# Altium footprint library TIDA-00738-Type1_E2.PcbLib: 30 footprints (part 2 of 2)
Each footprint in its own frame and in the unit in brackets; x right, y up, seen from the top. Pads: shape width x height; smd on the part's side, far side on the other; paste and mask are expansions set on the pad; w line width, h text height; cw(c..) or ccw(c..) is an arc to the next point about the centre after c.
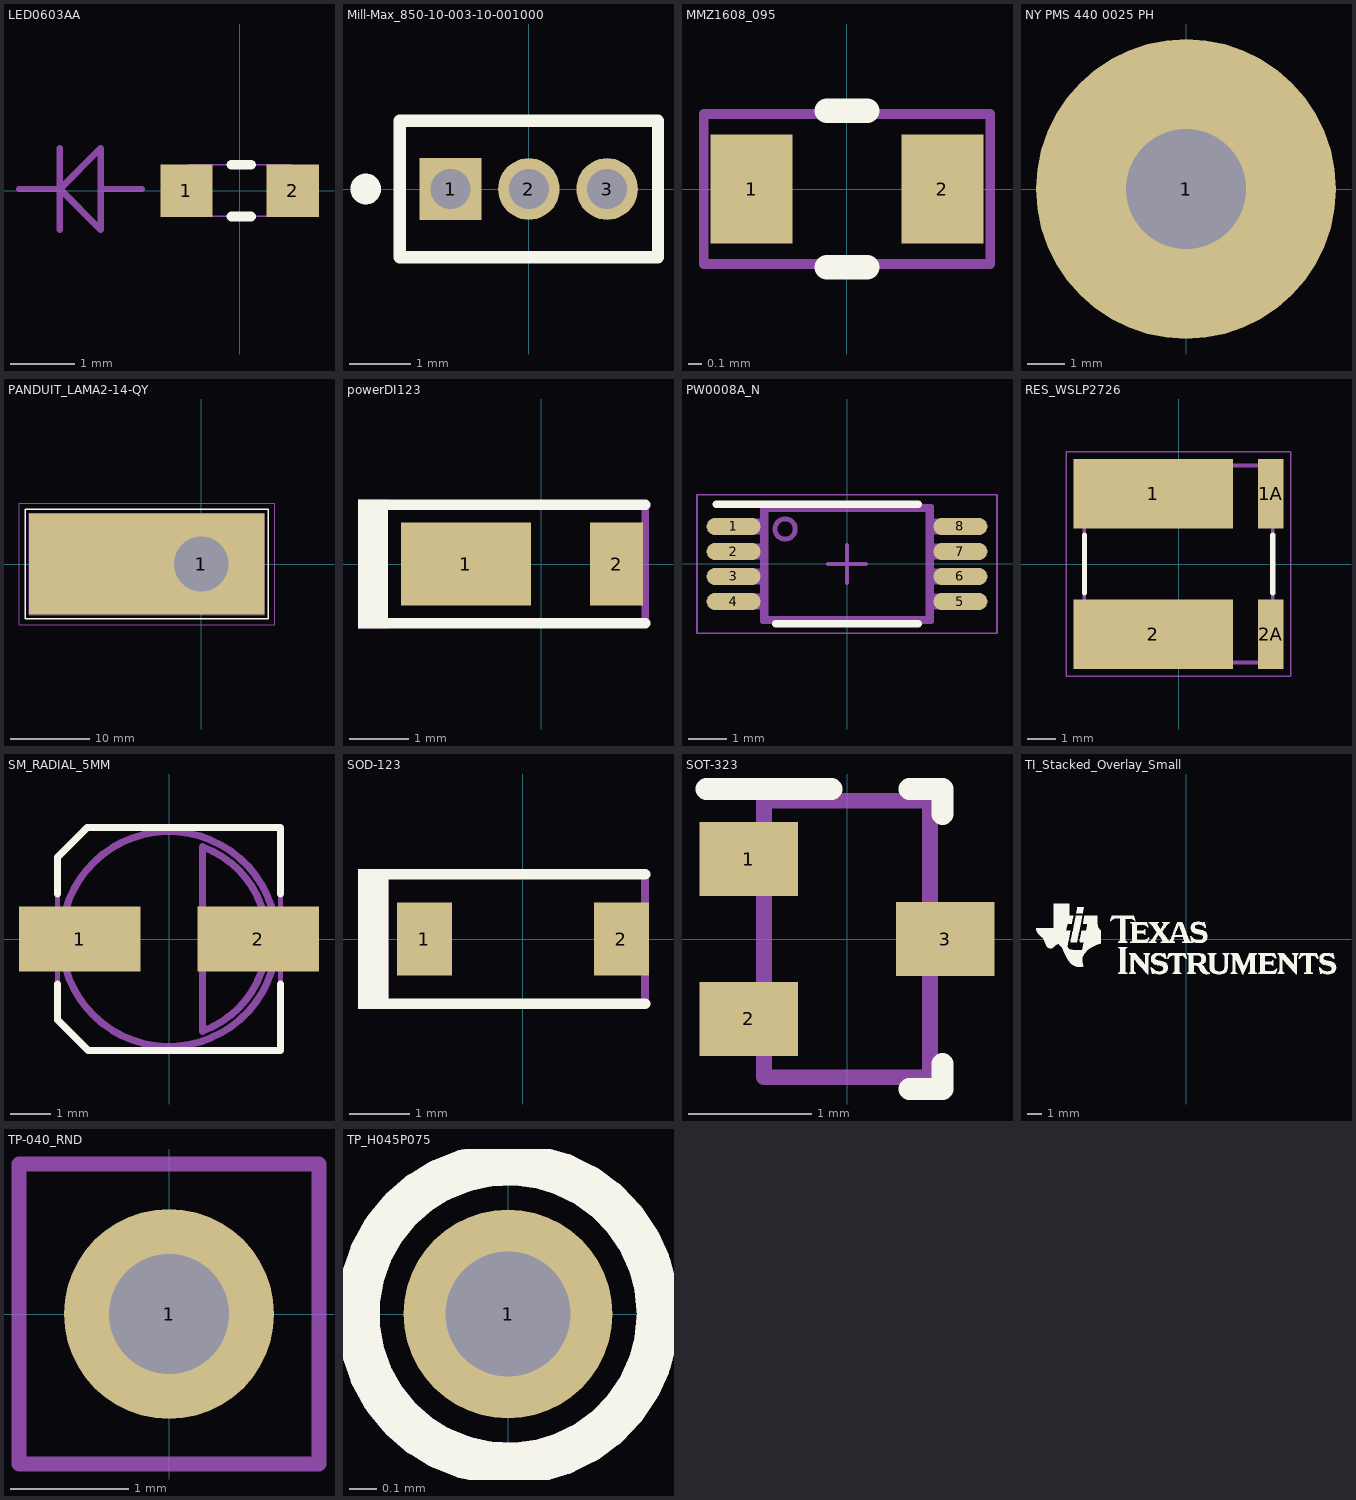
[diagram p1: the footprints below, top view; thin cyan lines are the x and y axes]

## LED0603AA [mil]
height 33.46
pads (2):
  rect 32x32 smd: 1(-32.48,0) 2(32.48,0)
Top Overlay:
  lines w6: -5,-15.75 7,-15.75 ; -5,15.75 7,15.75
Mechanical 15:
  lines w1: -31.5,-15.75 31.5,-15.75 31.5,15.75 -31.5,15.75 -31.5,-15.75
  lines w3.94: -134.79,0.96 -109.79,0.96 ; -109.79,-24.04 -109.79,25.96 ; -84.79,0.96 -59.79,0.96 ; -109.79,0.96 -84.79,25.96 -84.79,-24.04 -109.79,0.96

## Mill-Max_850-10-003-10-001000 [mm] "Header, 1.27 mm, 3x1, Gold, Straight, TH"
height 5.21
pads (3):
  rect 1x1 hole 0.65: 1(-1.27,0)
  round 1 hole 0.65: 2(0,0) 3(1.27,0)
Top Overlay:
  circle w0.25: c-2.645,0 r0.125
  lines w0.2: -2.095,-1.105 -2.095,1.105 2.095,1.105 2.095,-1.105 -2.095,-1.105
Mechanical 5:
  lines w0.1: -2.095,-1.105 -2.095,1.105 2.095,1.105 2.095,-1.105 -2.095,-1.105
  text ".Designator" at -1,-0.3 h0.7
3D body: height 5.21, standoff -2.9, extent 0.445,-1.105 2.095,1.105
3D body: height 5.21, standoff -2.9, extent -0.825,-1.105 0.825,1.105
3D body: height 5.21, standoff -2.9, extent -2.095,-1.105 -0.445,1.105

## MMZ1608_095 [mm] "TDK"
height 0.95
pads (2):
  rect 0.6x0.8 smd: 1(-0.7,0) 2(0.7,0)
Top Overlay:
  lines w0.18: -0.15,-0.575 0.15,-0.575 ; -0.15,0.575 0.15,0.575
Mechanical 5:
  lines w0.07: -1.05,-0.55 -1.05,0.55 1.05,0.55 1.05,-0.55 -1.05,-0.55
  text ".Designator" at 0.635,0.381 h0.76
3D body: height 0.95, standoff 0, extent -0.874,-0.474 -0.501,0.474
3D body: height 0.95, standoff 0, extent -0.499,-0.474 0.499,0.474
3D body: height 0.95, standoff 0, extent 0.501,-0.474 0.874,0.474

## NY PMS 440 0025 PH [mm] "4-40 nylon screw and mounting hole"
height 1.905
pads (1):
  round 8 hole 3.2: 1(0,0)
Mechanical 5:
  circle w0.127: c0,0 r3.789
  text ".Designator" at -1.524,-0.508 h0.76
3D body: height 2.69, standoff -8.74, extent -3.302,-3.3 3.296,3.3

## PANDUIT_LAMA2-14-QY [mm] "MECHANICAL LUG ALUM 2-14 AWG,TH"
height 14
pads (1):
  rect 29.5x12.7 hole 6.858 copper offset -6.85,0: 1(0,0)
Top Overlay:
  lines w0.178: -22.1,-6.85 -22.1,6.85 8.4,6.85 8.4,-6.85 -22.1,-6.85
Mechanical 5:
  lines w0.127: -21.6,-6.35 7.9,-6.35 7.9,6.35 -21.6,6.35 -21.6,-6.35
  text "PRELIMINARY" at -10.922,-5.842 h0.76
  text ".Designator" at -3.048,-1.905 h0.76
Mechanical 15:
  lines w0.05: -22.87,-7.62 -22.87,7.62 9.17,7.62 9.17,-7.62 -22.87,-7.62
Mechanical 17:
  text "MAKE A FULL THERMAL PADSTACK" at -20.701,4.572 h1.02
3D body: height 14, standoff 0, extent -21.6,-6.35 7.9,6.35

## powerDI123 [mm] "Diodes Inc recommended land pattern, document number DS30628 Rev. 6-2"
height 1
pads (2):
  rect 2.2x1.4 smd: 1(-1.275,0)
  rect 0.9x1.4 smd: 2(1.275,0)
Top Overlay:
  rectangle: -3.099,-1.092 -2.591,1.092
  lines w0.178: -2.946,-1.003 1.759,-1.003 ; -2.946,1.003 1.759,1.003
Mechanical 5:
  rectangle: -3.099,-1.092 -2.591,1.092
  lines w0.127: -2.946,-1.003 1.759,-1.003 1.759,1.003 -2.946,1.003
  text ".Designator" at 0.457,0.348 h0.76
3D body: height 1, standoff 0, extent -2.375,-0.965 1.525,0.965

## PW0008A_N [mm] "TSOP, 8-Leads, Body 3x4.4mm, Pitch 0.65mm, IPC Medium Density"
height 1.2
pads (8):
  oval 1.4x0.45 smd: 1(-2.95,0.975) 2(-2.95,0.325) 3(-2.95,-0.325) 4(-2.95,-0.975) 5(2.95,-0.975) 6(2.95,-0.325) 7(2.95,0.325) 8(2.95,0.975)
Top Overlay:
  lines w0.2: -3.4,1.55 1.85,1.55 ; -1.85,-1.55 1.85,-1.55
Mechanical 5:
  lines w0.127: -2.2,-1.5 -2.11,-1.41 ; -2.2,-1.5 2.2,-1.5 ; -2.2,-1.5 -2.2,-1.125 ; -2.2,-1.125 -2.2,-0.825 ; -2.2,-1.125 -2.4,-1.125 -2.669,-1.125 -2.785,-1.125 -2.856,-1.125 -3.228,-1.125 -3.228,-0.825 -2.856,-0.825 -2.785,-0.825 -2.669,-0.825 -2.4,-0.825 -2.2,-0.825 ; -2.2,-0.825 -2.2,-0.475 ; -2.2,-0.475 -2.4,-0.475 -2.669,-0.475 -2.785,-0.475 -2.856,-0.475 -3.228,-0.475 -3.228,-0.175 -2.856,-0.175 -2.785,-0.175 -2.669,-0.175 -2.4,-0.175 -2.2,-0.175 ; -2.2,-0.475 -2.2,-0.175 ; -2.2,-0.175 -2.2,0.175 ; -2.2,0.175 -2.2,0.475 ; -2.2,0.175 -2.4,0.175 -2.669,0.175 -2.785,0.175 -2.856,0.175 -3.228,0.175 -3.228,0.475 -2.856,0.475 -2.785,0.475 -2.669,0.475 -2.4,0.475 -2.2,0.475 ; -2.2,0.475 -2.2,0.825 ; -2.2,0.825 -2.4,0.825 -2.669,0.825 -2.785,0.825 -2.856,0.825 -3.228,0.825 -3.228,1.125 -2.856,1.125 -2.785,1.125 -2.669,1.125 -2.4,1.125 -2.2,1.125 ; -2.2,0.825 -2.2,1.125 ; -2.2,1.125 -2.2,1.5 ; -2.2,1.5 -2.11,1.41 ; -2.2,1.5 2.2,1.5 ; -2.11,-1.41 -2.11,1.41 ; -2.11,-1.41 2.11,-1.41 ; -2.11,1.41 2.11,1.41 ; 2.11,-1.41 2.11,1.41 ; 2.11,-1.41 2.2,-1.5 ; 2.11,1.41 2.2,1.5 ; 2.2,-1.5 2.2,-1.125 ; 2.2,-1.125 2.2,-0.825 ; 2.2,-1.125 2.4,-1.125 2.669,-1.125 2.785,-1.125 2.856,-1.125 3.228,-1.125 3.228,-0.825 2.856,-0.825 2.785,-0.825 2.669,-0.825 2.4,-0.825 2.2,-0.825 ; 2.2,-0.825 2.2,-0.475 ; 2.2,-0.475 2.2,-0.175 ; 2.2,-0.475 2.4,-0.475 2.669,-0.475 2.785,-0.475 2.856,-0.475 3.228,-0.475 3.228,-0.175 2.856,-0.175 2.785,-0.175 2.669,-0.175 2.4,-0.175 2.2,-0.175 ; 2.2,-0.175 2.2,0.175 ; 2.2,0.175 2.4,0.175 2.669,0.175 2.785,0.175 2.856,0.175 3.228,0.175 3.228,0.475 2.856,0.475 2.785,0.475 2.669,0.475 2.4,0.475 2.2,0.475 ; 2.2,0.175 2.2,0.475 ; 2.2,0.475 2.2,0.825 ; 2.2,0.825 2.4,0.825 2.669,0.825 2.785,0.825 2.856,0.825 3.228,0.825 3.228,1.125 2.856,1.125 2.785,1.125 2.669,1.125 2.4,1.125 2.2,1.125 ; 2.2,0.825 2.2,1.125 ; 2.2,1.125 2.2,1.5 ; -1.61,0.646 cw(c-1.61,0.91) -1.61,1.173 cw(c-1.61,0.91) -1.61,0.646
  text ".Designator" at 1.194,0.342 h0.76
Mechanical 15:
  lines w0.05: -3.9,-1.8 -3.9,1.8 3.9,1.8 3.9,-1.8 -3.9,-1.8
  lines w0.1: -0.5,0 0.5,0 ; 0,-0.5 0,0.5
3D body: height 1.2, standoff 0, extent -3.208,-1.5 3.208,1.5

## RES_WSLP2726 [mil]
height 149
pads (4):
  rect 220x96 smd: 1(-35,97) 2(-35,-97)
  rect 35x96 smd: 1A(127.5,97) 2A(127.5,-97)
Top Overlay:
  lines w7: -130,-40 -130,40 ; 130,-40 130,40
Mechanical 5:
  lines w5: -130,-136 -130,136 130,136 130,-136 -130,-136
  text ".Designator" at 16,-50 h30
Mechanical 15:
  lines w1.97: -154.84,-154.84 -154.84,154.84 154.84,154.84 154.84,-154.84 -154.84,-154.84
3D body: height 149, standoff 0, extent -130,-136 130,136

## SM_RADIAL_5MM [mm] "Nichicon 5x5.8"
height 6.1
pads (2):
  rect 3x1.6 smd: 1(-2.2,0) 2(2.2,0)
Top Overlay:
  lines w0.178: -2.75,-1.108 -2.75,-1.992 -1.992,-2.75 2.75,-2.75 2.75,-1.108 ; -2.75,1.108 -2.75,2.019 -2.019,2.75 2.75,2.75 2.75,1.118
Mechanical 5:
  lines w0.127: -2.75,-1.992 -1.992,-2.75 2.75,-2.75 2.75,2.75 -2.019,2.75 -2.75,2.019 -2.75,-1.992
  text ".Designator" at -1.016,-0.508 h0.76
Mechanical 13:
  circle w0.178: c0,0 r2.65
  lines w0.178: 0.827,-2.273 ccw(c0,0) 0.827,2.273 0.827,-2.273
3D body: height 1, standoff 0, extent -2.751,-2.751 2.751,2.751
3D body: height 6.1, standoff 6, extent 0.827,-2.277 2.432,2.277
3D body: height 6.1, standoff 1, extent -2.658,-2.658 2.658,2.658

## SOD-123 [mm] "On Semi recommended land pattern"
height 1.35
pads (2):
  rect 0.915x1.22 smd: 1(-1.637,0) 2(1.637,0)
Top Overlay:
  rectangle: -2.743,-1.168 -2.235,1.168
  lines w0.178: -2.413,-1.079 2.032,-1.079 ; -2.413,1.079 2.032,1.079
Mechanical 5:
  rectangle: -2.743,-1.168 -2.235,1.168
  lines w0.127: -2.413,-1.079 2.032,-1.079 2.032,1.079 -2.413,1.079
  text ".Designator" at -0.889,-0.508 h0.76
3D body: height 1.35, standoff 0, extent -1.932,-0.9 1.932,0.9

## SOT-323 [mm] "Zetex recommended land pattern.  March 2007"
height 1.1
pads (3):
  rect 0.8x0.6 smd: 1(-0.8,0.65) 2(-0.8,-0.65) 3(0.8,0)
Top Overlay:
  lines w0.178: -1.143,1.219 -0.127,1.219 ; 0.508,-1.219 0.775,-1.219 0.775,-1.016 ; 0.508,1.219 0.775,1.219 0.775,1.016
Mechanical 5:
  lines w0.127: -1.125,-0.8 -1.125,-0.5 -0.975,-0.5 -0.935,-0.5 -0.884,-0.5 -0.725,-0.5 -0.675,-0.5 -0.675,-0.8 -0.725,-0.8 -0.884,-0.8 -0.935,-0.8 -0.975,-0.8 -1.125,-0.8 ; -1.125,0.5 -1.125,0.8 -0.975,0.8 -0.935,0.8 -0.884,0.8 -0.725,0.8 -0.675,0.8 -0.675,0.5 -0.725,0.5 -0.884,0.5 -0.935,0.5 -0.975,0.5 -1.125,0.5 ; -0.675,-1.125 -0.675,1.125 0.675,1.125 0.675,-1.125 -0.675,-1.125 ; 0.675,-0.15 0.725,-0.15 0.884,-0.15 0.935,-0.15 0.975,-0.15 1.125,-0.15 1.125,0.15 0.975,0.15 0.935,0.15 0.884,0.15 0.725,0.15 0.675,0.15 0.675,-0.15
  text ".Designator" at 0.406,-0.66 h0.76
3D body: height 1.13, standoff 0.02, extent -1.125,-1.125 1.125,1.125

## TI_Stacked_Overlay_Small [mm]
Top Overlay:
  drawing of 18 lines, arcs and shapes, not listed

## TP-040_RND [mil]
height 33.46
pads (1):
  round 70 / inner round 62 / far side round 62 hole 40: 1(0,0)
Mechanical 5:
  lines w5: -50,-50 -50,50 50,50 50,-50 -50,-50

## TP_H045P075 [mm] "TP_H0.45P0.75"
height 5.21
pads (1):
  round 0.75 hole 0.45: 1(0,0)
Top Overlay:
  circle w0.152: c0,0 r0.539
Mechanical 5:
  circle w0.152: c0,0 r0.539
  text ".designator" at 0.889,0.889 h0.76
